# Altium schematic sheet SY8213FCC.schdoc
size 127 x 101 mm
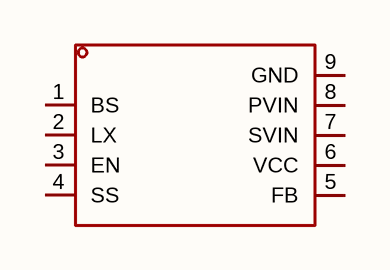
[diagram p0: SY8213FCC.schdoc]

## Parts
U?  sy8213fcc  [SOIC-8_L4.9-W3.9-P1.27-LS6.0-BL-EP]  (value not drawn)

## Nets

Not connected (* = marked no-connect by the designer): U? 1(BS) 2(LX) 3(EN) 4(SS) 5(FB) 6(VCC) 7(SVIN) 8(PVIN) 9(GND)

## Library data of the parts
U? = sy8213fcc: 功能类型:降压型;工作电压:4.5V~30V;输出电压:-;输出电流:3A;输出类型:可调;; Manufacturer: Silergy(矽力杰); AddInBom: yes; ModelId: 3febf2d495b54c0da7c8bb4287865e8b; ModelTransform: 192.913,236.22,0,0,0,0,0,0,0; Function: 降压型; Output Current: 3A; Frequency - Switching: 500kHz; Synchronous Rectifier: 是; Number of Outputs: 1; Topology: 降压式; Quiescent Current: 200uA; Switch tube (built-in/external): 内置; Output Type: 可调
